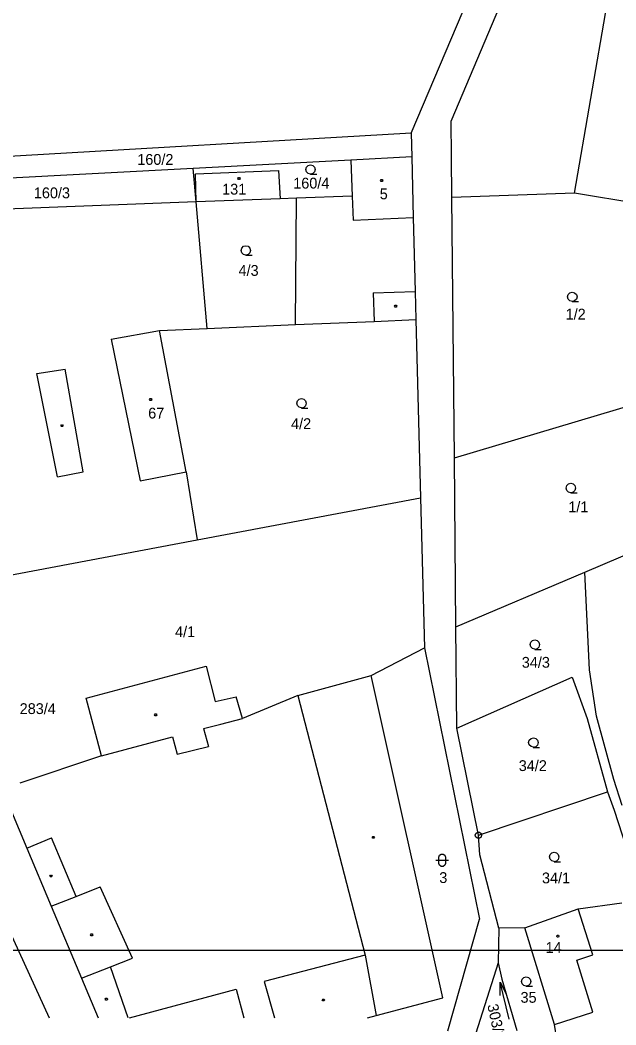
# Model space of a CAD drawing. Extents: x -779723 to -777378, y -1011169 to -1009297.
# Drawn here: x -779195.8 to -779102, y -1010279.6 to -1010121.5 of the extents above; entities that cross this region are included whole.
import ezdxf

# ---------------------------------------------------------------- set-up
doc = ezdxf.new("R2010")
doc.units = 0
for name, color, linetype in [('Default', 7, 'Continuous'), ('KN_HRANICE', 7, 'Continuous'), ('KN_KULTURY', 7, 'Continuous'), ('KN_PARCELY', 7, 'Continuous'), ('KN_SLUCKY', 7, 'Continuous'), ('LEGENDA', 7, 'Continuous')]:
    doc.layers.add(name, color=color, linetype=linetype)

# ---------------------------------------------------------------- blocks, each defined once
blk = doc.blocks.new('304')
at = {"layer": 'Default'}
blk.add_lwpolyline([(0, 0), (-0.38, 0.1), (-0.65, 0.37), (-0.75, 0.74), (-0.65, 1.11), (-0.38, 1.38), (-0.01, 1.48), (0.36, 1.38), (0.63, 1.11), (0.73, 0.73), (0.63, 0.35), (0.36, 0.08), (-0.02, -0.02), (0.98, -0.02)], dxfattribs=at)
blk = doc.blocks.new('316')
at = {"layer": 'Default'}
for points in [[(-0.5, 1.5), (-0.4, 1.79), (-0.15, 1.97), (0.16, 1.97), (0.41, 1.79), (0.51, 1.5), (0.51, 0.5), (0.41, 0.21), (0.16, 0.03), (-0.15, 0.03), (-0.4, 0.21), (-0.5, 0.5), (-0.5, 1.5)], [(-1, 1), (0.27, 1), (1, 1)]]:
    blk.add_lwpolyline(points, dxfattribs=at)
blk = doc.blocks.new('802')
at = {"layer": 'Default'}
blk.add_line((-3, 0), (3, 0), dxfattribs=at)
blk.add_lwpolyline([(1, 0.5), (3, 0), (1, -0.5)], dxfattribs=at)
blk = doc.blocks.new('402')
at = {"layer": 'Default'}
blk.add_lwpolyline([(0.09, 0.15), (0.18, 0), (0.09, -0.15), (-0.09, -0.15), (-0.18, 0), (-0.09, 0.15), (0.09, 0.15)], dxfattribs=at)
blk = doc.blocks.new('105')
at = {"layer": 'Default'}
blk.add_line((-0.12, 0), (0.12, 0), dxfattribs=at)
blk.add_lwpolyline([(0.15, 0.48), (0.4, 0.3), (0.5, 0.01), (0.4, -0.28), (0.15, -0.46), (-0.16, -0.46), (-0.41, -0.28), (-0.51, 0.01), (-0.41, 0.3), (-0.16, 0.48), (0.15, 0.48)], dxfattribs=at)

msp = doc.modelspace()

# ---------------------------------------------------------------- linework, layer by layer
at = {"layer": 'KN_HRANICE'}
for p, q in [((-779134.25, -1010139.27), (-779120.37, -1010106.68)), ((-779127.92, -1010137.41), (-779118.39, -1010114.83)), ((-779127.87, -1010142.99), (-779127.92, -1010137.41)), ((-779134.25, -1010139.27), (-779212.16, -1010143.8)), ((-779134.25, -1010139.27), (-779134.15, -1010143.02)), ((-779143.73, -1010143.53), (-779168.53, -1010144.84)), ((-779134.15, -1010143.02), (-779143.73, -1010143.53)), ((-779143.73, -1010143.53), (-779143.53, -1010149.2)), ((-779134.15, -1010143.02), (-779133.9, -1010152.56)), ((-779127.81, -1010149.44), (-779127.87, -1010142.99)), ((-779168.53, -1010144.84), (-779209.48, -1010147.01)), ((-779168.07, -1010150.12), (-779168.53, -1010144.84)), ((-779168.2, -1010145.69), (-779155.14, -1010145.17)), ((-779155.14, -1010145.17), (-779154.88, -1010149.63)), ((-779168.07, -1010150.12), (-779168.2, -1010145.69)), ((-779108.53, -1010148.76), (-779127.81, -1010149.44)), ((-779096.36, -1010150.77), (-779108.53, -1010148.76)), ((-779168.07, -1010150.12), (-779218.39, -1010152.01)), ((-779154.88, -1010149.63), (-779168.07, -1010150.12)), ((-779166.33, -1010170.02), (-779168.07, -1010150.12)), ((-779152.27, -1010149.53), (-779154.88, -1010149.63)), ((-779152.43, -1010169.43), (-779152.27, -1010149.53)), ((-779143.53, -1010149.2), (-779152.27, -1010149.53)), ((-779127.44, -1010190.39), (-779127.81, -1010149.44)), ((-779133.9, -1010152.56), (-779133.6, -1010164.22)), ((-779133.6, -1010164.22), (-779133.49, -1010168.63)), ((-779152.43, -1010169.43), (-779140.08, -1010168.91)), ((-779140.08, -1010168.91), (-779133.49, -1010168.63)), ((-779133.49, -1010168.63), (-779132.76, -1010196.68)), ((-779173.84, -1010170.34), (-779166.33, -1010170.02)), ((-779169.66, -1010192.59), (-779173.84, -1010170.34)), ((-779166.33, -1010170.02), (-779152.43, -1010169.43)), ((-779127.44, -1010190.39), (-779090.53, -1010179.36)), ((-779127.2, -1010217), (-779127.44, -1010190.39)), ((-779169.66, -1010192.59), (-779167.91, -1010203.3)), ((-779167.91, -1010203.3), (-779132.76, -1010196.68)), ((-779132.76, -1010196.68), (-779132.14, -1010220.3)), ((-779106.91, -1010208.39), (-779091.64, -1010201.91)), ((-779207.96, -1010210.85), (-779167.91, -1010203.3)), ((-779127.2, -1010217), (-779106.91, -1010208.39)), ((-779106.16, -1010223.74), (-779106.91, -1010208.39)), ((-779127.06, -1010232.92), (-779127.2, -1010217)), ((-779140.53, -1010224.66), (-779132.14, -1010220.3)), ((-779132.14, -1010220.3), (-779123.49, -1010263.01)), ((-779185.42, -1010228.21), (-779166.52, -1010223.19)), ((-779166.52, -1010223.19), (-779165.11, -1010228.72)), ((-779152.1, -1010227.79), (-779140.53, -1010224.66)), ((-779129.26, -1010275.39), (-779140.53, -1010224.66)), ((-779105.07, -1010231.05), (-779106.16, -1010223.74)), ((-779127.06, -1010232.92), (-779108.9, -1010224.93)), ((-779108.9, -1010224.93), (-779106.53, -1010231.41)), ((-779152.1, -1010227.79), (-779160.79, -1010231.43)), ((-779182.98, -1010237.3), (-779185.42, -1010228.21)), ((-779165.11, -1010228.72), (-779161.77, -1010228)), ((-779160.79, -1010231.43), (-779161.77, -1010228)), ((-779106.53, -1010231.41), (-779103.32, -1010242.93)), ((-779102.33, -1010241), (-779105.07, -1010231.05)), ((-779123.64, -1010249.79), (-779127.06, -1010232.92)), ((-779182.98, -1010237.3), (-779195.85, -1010241.6)), ((-779101.02, -1010245.11), (-779102.33, -1010241)), ((-779198.63, -1010242.53), (-779194.73, -1010251.82)), ((-779123.64, -1010249.79), (-779103.32, -1010242.93)), ((-779103.32, -1010242.93), (-779102.28, -1010245.85)), ((-779102.28, -1010245.85), (-779098.52, -1010257.5)), ((-779123.44, -1010252.85), (-779123.64, -1010249.79)), ((-779194.73, -1010251.82), (-779190.9, -1010260.95)), ((-779120.42, -1010264.41), (-779123.44, -1010252.85)), ((-779190.9, -1010260.95), (-779186.13, -1010272.3)), ((-779107.93, -1010261.36), (-779101.09, -1010260.41)), ((-779116.32, -1010264.37), (-779107.93, -1010261.36)), ((-779198.24, -1010263.13), (-779191.22, -1010278.51)), ((-779128.47, -1010280.58), (-779123.49, -1010263.01)), ((-779120.42, -1010264.41), (-779120.56, -1010269.87)), ((-779116.32, -1010264.37), (-779120.42, -1010264.41)), ((-779111.69, -1010279.58), (-779116.32, -1010264.37)), ((-779120.56, -1010269.87), (-779125.19, -1010284.44)), ((-779120.56, -1010269.87), (-779119.96, -1010272.44)), ((-779186.13, -1010272.3), (-779183.53, -1010278.51)), ((-779119.96, -1010272.44), (-779117.61, -1010280.51)), ((-779139.76, -1010278.16), (-779129.26, -1010275.39)), ((-779141.1, -1010278.51), (-779139.76, -1010278.16)), ((-779111.28, -1010281.87), (-779111.69, -1010279.58))]:
    msp.add_line(p, q, dxfattribs=at)
at = {"layer": 'KN_SLUCKY'}
for p, q in [((-779108.53, -1010148.76), (-779103.38, -1010118.93)), ((-779143.53, -1010149.2), (-779143.39, -1010153)), ((-779143.39, -1010153), (-779133.9, -1010152.56)), ((-779140.21, -1010164.42), (-779133.6, -1010164.22)), ((-779140.21, -1010164.42), (-779140.08, -1010168.91)), ((-779181.46, -1010171.71), (-779173.84, -1010170.34)), ((-779181.46, -1010171.71), (-779176.88, -1010194.03)), ((-779193.17, -1010177.11), (-779188.72, -1010176.41)), ((-779189.9, -1010193.37), (-779193.17, -1010177.11)), ((-779185.87, -1010192.57), (-779188.72, -1010176.41)), ((-779189.9, -1010193.37), (-779185.87, -1010192.57)), ((-779176.88, -1010194.03), (-779169.66, -1010192.59)), ((-779152.1, -1010227.79), (-779141.46, -1010268.66)), ((-779166.93, -1010233.01), (-779164.21, -1010232.28)), ((-779164.21, -1010232.28), (-779160.79, -1010231.43)), ((-779166.93, -1010233.01), (-779166.12, -1010235.81)), ((-779182.98, -1010237.3), (-779171.83, -1010234.32)), ((-779171.83, -1010234.32), (-779171.09, -1010237.01)), ((-779171.09, -1010237.01), (-779166.12, -1010235.81)), ((-779194.73, -1010251.82), (-779190.86, -1010250.19)), ((-779186.99, -1010259.4), (-779190.86, -1010250.19)), ((-779190.9, -1010260.95), (-779186.99, -1010259.4)), ((-779186.99, -1010259.4), (-779183.21, -1010257.9)), ((-779178.12, -1010269.14), (-779183.21, -1010257.9)), ((-779105.66, -1010268.59), (-779107.93, -1010261.36)), ((-779141.46, -1010268.66), (-779157.38, -1010272.82)), ((-779141.46, -1010268.66), (-779139.76, -1010278.16)), ((-779108.14, -1010269.47), (-779105.66, -1010268.59)), ((-779186.13, -1010272.3), (-779181.59, -1010270.51)), ((-779181.59, -1010270.51), (-779178.12, -1010269.14)), ((-779178.77, -1010278.51), (-779181.59, -1010270.51)), ((-779105.62, -1010277.63), (-779108.14, -1010269.47)), ((-779157.38, -1010272.82), (-779155.74, -1010278.51)), ((-779178.58, -1010278.51), (-779161.78, -1010273.99)), ((-779161.78, -1010273.99), (-779160.56, -1010278.51)), ((-779111.69, -1010279.58), (-779105.62, -1010277.63))]:
    msp.add_line(p, q, dxfattribs=at)
at = {"layer": 'LEGENDA'}
msp.add_lwpolyline([(-779530.66, -1010687.91), (-778936.66, -1010687.91), (-778936.66, -1010267.91), (-779530.66, -1010267.91)], close=True, dxfattribs=at)

# ---------------------------------------------------------------- block references
at = {"layer": 'KN_KULTURY'}
for name, p in [('304', (-779150.08, -1010145.74)), ('402', (-779161.34, -1010146.42)), ('402', (-779138.89, -1010146.76)), ('304', (-779160.25, -1010158.48)), ('304', (-779108.86, -1010165.78)), ('402', (-779136.69, -1010166.53)), ('402', (-779175.24, -1010181.2)), ('304', (-779151.49, -1010182.54)), ('402', (-779189.2, -1010185.33)), ('304', (-779109.08, -1010195.88)), ('304', (-779114.77, -1010220.52)), ('402', (-779174.46, -1010230.82)), ('304', (-779114.99, -1010235.94)), ('402', (-779140.18, -1010250.11)), ('316', (-779129.36, -1010254.72)), ('304', (-779111.73, -1010253.93)), ('402', (-779190.93, -1010256.2)), ('402', (-779184.52, -1010265.45)), ('402', (-779111.15, -1010265.67)), ('304', (-779116.12, -1010273.53)), ('402', (-779182.2, -1010275.59)), ('402', (-779148.04, -1010275.71))]:
    msp.add_blockref(name, p, dxfattribs=at)
at = {"layer": 'KN_KULTURY', "rotation": 103.648065}
msp.add_blockref('802', (-779119.52, -1010275.84), dxfattribs=at)
at = {"layer": 'KN_PARCELY'}
msp.add_blockref('105', (-779123.64, -1010249.79), dxfattribs=at)

# ---------------------------------------------------------------- texts
for s, p in [('160/2', (-779177.35, -1010144.28)), ('160/4', (-779152.8, -1010148.01)), ('160/3', (-779193.63, -1010149.54)), ('131', (-779163.99, -1010148.96)), ('5', (-779139.18, -1010149.7)), ('4/3', (-779161.41, -1010161.75)), ('1/2', (-779109.92, -1010168.63)), ('67', (-779175.63, -1010184.2)), ('4/2', (-779153.14, -1010185.86)), ('1/1', (-779109.5, -1010198.96)), ('4/1', (-779171.4, -1010218.61)), ('34/3', (-779116.82, -1010223.42)), ('283/4', (-779195.86, -1010230.71)), ('34/2', (-779117.3, -1010239.68)), ('3', (-779129.81, -1010257.3)), ('34/1', (-779113.64, -1010257.35)), ('14', (-779113.08, -1010268.31)), ('35', (-779117.02, -1010276.15))]:
    msp.add_text(s, height=1.7, dxfattribs=at).set_placement(p)
msp.add_text('303/3', height=1.7, rotation=282.296, dxfattribs=at).set_placement((-779122.26, -1010276.53))

doc.saveas('drawing.dxf')
